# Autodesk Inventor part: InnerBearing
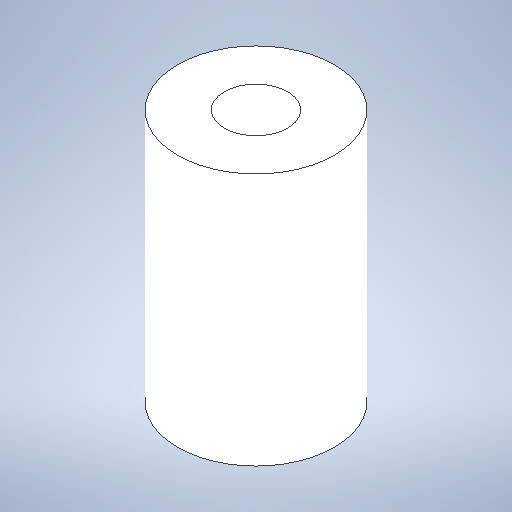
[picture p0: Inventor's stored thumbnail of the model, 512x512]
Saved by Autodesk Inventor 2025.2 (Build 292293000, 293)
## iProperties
Created: 2025-09
Part Number: InnerBearing
Material: Generic
Document SubType Name: Modeling
Designer: tyler
Density: 1 g/cm^3
Appearance: Default
Author: tyler
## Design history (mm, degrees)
sketch "Sketch1"
  geometry: C1 r 1.587 at (0, 0); C2 r 3.937 at (0, 0); 1 further point
  constraints: 2 centre point, 2 coincident
  dimensions: "d0" = 3.175 diameter of C1; "d1" = 7.874 diameter of C2
extrude "Extrusion1" new body sketch "Sketch1" distance "d2" = 12.7; taper "d3" = 0 deg
body "Solid1"
